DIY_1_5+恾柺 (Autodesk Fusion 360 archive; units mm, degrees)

design "DIY_1_5"
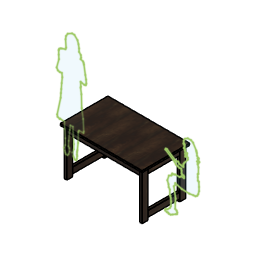
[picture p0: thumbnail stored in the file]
work_plane "作業平面" AlongDistance 675 (= "takasa - 25 mm") named "h1"
sketch "スケッチ2" plane through (0, 0, 675) normal (0, 0, 1) x axis (1, 0, 0)
  line L1 (600, 350) -> (-600, 350)
  line L2 (600, -350) -> (600, 350)
  line L3 (-600, -350) -> (600, -350)
  line L4 (-600, 350) -> (-600, -350)
  line L5 (0, 22.5) -> (0, 1.75)
  line L6 (22.5, 0) -> (1.75, 0)
  point P2 (-600, 350)
  point P3 (600, 350)
  point P5 (-600, -350)
  horizontal L1
  vertical L2
  horizontal L3
  vertical L4
  symmetric L2 L4 L5
  symmetric L1 L3 L6
  dimension "x1" distance P2 P3 = 1200 (= "haba")
  dimension "y1" distance P2 P5 = 700 (= "oku")
  dimension "takasa" value = 700
  dimension "haba" value = 1200
  dimension "oku" value = 700
extrude "押し出し1" new body sketch "スケッチ2" profile of L1 L2 L3 L4 along normal blind 25
sketch "スケッチ3" plane through (0, 0, 675) normal (0, 0, -1) x axis (1, 0, 0)
  line L1 (-600, 350) -> (600, 350)
  line L2 (-600, -350) -> (-600, 350)
  line L3 (600, -350) -> (-600, -350)
  line L4 (600, 350) -> (600, -350)
  line L5 (570, 320) -> (532, 320)
  line L6 (570, 231) -> (570, 320)
  line L7 (532, 231) -> (570, 231)
  line L8 (532, 320) -> (532, 231)
  point P6 (532, 320)
  point P7 (570, 320)
  point P8 (570, 231)
  horizontal L5
  vertical L6
  horizontal L7
  vertical L8
  dimension "d6" distance P6 P7 = 38
  dimension "d7" distance P7 P8 = 89
  dimension "d8" distance L1 L5 = 30
  dimension "d9" distance L4 L6 = 30
extrude "押し出し1" new body sketch "スケッチ3" profile of L5 L6 L7 L8 to an object
work_point "作業点5"
fillet "フィレット1" radius 3
component_from_bodies "ボディ -> コンポーネント1"
mirror_component "コンポーネントをミラー化1"
derived_instance "DerivedInstance1"
derived_instance "DerivedInstance2"
remove_instance "RemoveInstance1"
mirror_component "コンポーネントをミラー化2"
derived_instance "DerivedInstance3"
derived_instance "DerivedInstance4"
sketch "スケッチ4" plane through (0, 0, 675) normal (0, 0, 1) x axis (1, 0, 0)
  line L1 (-532, -234) -> (-532, -317)
  line L2 (532, -234) -> (532, -317)
  line L3 (532, -315) -> (-532, -315)
  line L4 (532, -277) -> (532, -315)
  line L5 (-532, -277) -> (532, -277)
  line L6 (-532, -315) -> (-532, -277)
  line L7 (-600, -350) -> (600, -350)
  point P8 (532, -277)
  point P6 (-532, -315)
  horizontal L3
  vertical L4
  horizontal L5
  vertical L6
  coincident L2 P8
  coincident L1 P6
  dimension "d14" distance L3 L7 = 35
  dimension "d15" distance L3 L5 = 38
extrude "押し出し1" new body sketch "スケッチ4" profile of L3 L4 L5 L6 against normal blind 89
work_point "作業点3"
fillet "フィレット1" radius 3
mirror_component "コンポーネントをミラー化3"
derived_instance "DerivedInstance5"
sketch "スケッチ5" plane through (0, 0, 675) normal (0, 0, 1) x axis (1, 0, 0)
  line L1 (567, -231) -> (535, -231)
  line L2 (567, 231) -> (535, 231)
  line L3 (532, -231) -> (570, -231)
  line L4 (532, 231) -> (532, -231)
  line L5 (570, 231) -> (532, 231)
  line L6 (570, -231) -> (570, 231)
  line L7 (600, -350) -> (600, 350)
  point P8 (532, 231)
  point P6 (570, -231)
  horizontal L3
  vertical L4
  horizontal L5
  vertical L6
  coincident L2 P8
  coincident L1 P6
  dimension "d20" distance L6 L7 = 30
  dimension "d21" distance L4 L6 = 38
extrude "押し出し1" new body sketch "スケッチ5" profile of L3 L4 L5 L6 against normal blind 89
fillet "フィレット1" radius 3
mirror_component "コンポーネントをミラー化4"
derived_instance "DerivedInstance6"
work_point "作業点1"
chamfer "面取り1" distance 5
chamfer "面取り2" distance 3
sketch "スケッチ6" plane through (0, 231, 0) normal (0, -1, 0) x axis (1, 0, 0)
  line L1 (535, 0) -> (535, 675)
  line L2 (567, 0) -> (535, 0)
  line L3 (567, 675) -> (567, 0)
  line L4 (535, 675) -> (567, 675)
  line L5 (570, 0) -> (570, 675)
  line L6 (532, 675) -> (532, 0)
  line L7 (532, 35) -> (570, 35)
  line L8 (532, 124) -> (532, 35)
  line L9 (570, 124) -> (532, 124)
  line L10 (570, 35) -> (570, 124)
  point P12 (532, 124)
  point P10 (570, 35)
  point P13 (570, 124)
  horizontal L7
  vertical L8
  horizontal L9
  vertical L10
  coincident L6 P12
  coincident L5 P10
  dimension "d72" distance L2 L7 = 35
  dimension "d73" distance P10 P13 = 89
extrude "押し出し1" new body sketch "スケッチ6" profile of L1 L3 L7 L8 L9 L10 to an object
fillet "フィレット1" radius 3
mirror_component "コンポーネントをミラー化5"
derived_instance "DerivedInstance7"
sketch "スケッチ7" plane through (0, 0, 0) normal (0, 1, 0) x axis (1, 0, 0)
  line L1 (-500, 0) -> (0, 0)
  line L2 (-500, -400) -> (-500, 0)
  line L3 (-300, -400) -> (-500, -400)
  line L4 (-300, -1600) -> (-300, -400)
  line L5 (0, -1600) -> (-300, -1600)
  line L6 (0, 0) -> (0, -1600)
  point P1 (0, 0)
  point P2 (0, 0)
  point P8 (0, 0)
  point P3 (-500, 0)
  point P4 (-500, -400)
  point P7 (0, -1600)
  point P6 (-300, -1600)
  point P5 (-300, -400)
  coincident P1 P2
  horizontal L1
  perpendicular L1 L2
  perpendicular L2 L3
  perpendicular L3 L4
  perpendicular L4 L5
  coincident P1 P8
  perpendicular L1 L6
  dimension "d139" distance P3 P4 = 400
  dimension "d140" distance P7 P8 = 1600
  dimension "d141" distance P6 P7 = 300
  dimension "d142" distance P4 P5 = 200
sketch "スケッチ8" plane through (0, 0, 0) normal (0, 1, 0) x axis (1, 0, 0)
  line L1 (-945.136, -1302.6809) -> (-960.979, -1290.0486)
  line L2 (-925.1626, -1311.6484) -> (-945.136, -1302.6809)
  line L3 (-870.2935, -1330.2367) -> (-925.1626, -1311.6484)
  line L4 (-861.6507, -1353.6859) -> (-870.2935, -1330.2367)
  line L5 (-869.2291, -1456.8486) -> (-861.6507, -1353.6859)
  line L6 (-862.3124, -1501.2995) -> (-869.2291, -1456.8486)
  line L7 (-837.5923, -1542.7914) -> (-862.3124, -1501.2995)
  line L8 (-774.327, -1578.353) -> (-837.5923, -1542.7914)
  line L9 (-739.7271, -1577.3626) -> (-774.327, -1578.353)
  line L10 (-694.2446, -1531.9253) -> (-739.7271, -1577.3626)
  line L11 (-680.4071, -1488.4566) -> (-694.2446, -1531.9253)
  line L12 (-671.5136, -1439.0667) -> (-680.4071, -1488.4566)
  line L13 (-671.5136, -1395.6021) -> (-671.5136, -1439.0667)
  line L14 (-645.8072, -1367.9426) -> (-671.5136, -1395.6021)
  line L15 (-641.8536, -1336.3294) -> (-645.8072, -1367.9426)
  line L16 (-648.7744, -1315.5855) -> (-641.8536, -1336.3294)
  line L17 (-613.78, -1303.9149) -> (-648.7744, -1315.5855)
  line L18 (-604.9851, -1288.5783) -> (-613.78, -1303.9149)
  line L19 (-600.3288, -1270.1462) -> (-604.9851, -1288.5783)
  line L20 (-579.8746, -1149.1493) -> (-600.3288, -1270.1462)
  line L21 (-569.1605, -1095.7966) -> (-579.8746, -1149.1493)
  line L22 (-565.881, -1046.2311) -> (-569.1605, -1095.7966)
  line L23 (-573.3812, -1022.4984) -> (-565.881, -1046.2311)
  line L24 (-594.7149, -1016.7047) -> (-573.3812, -1022.4984)
  line L25 (-633.6876, -1022.5004) -> (-594.7149, -1016.7047)
  line L26 (-649.1196, -1028.5674) -> (-633.6876, -1022.5004)
  line L27 (-645.5524, -968.1152) -> (-649.1196, -1028.5674)
  line L28 (-649.1607, -952.4859) -> (-645.5524, -968.1152)
  line L29 (-637.5096, -875.829) -> (-649.1607, -952.4859)
  line L30 (-632.7588, -703.3576) -> (-637.5096, -875.829)
  line L31 (-611.7457, -575.5405) -> (-632.7588, -703.3576)
  line L32 (-602.2974, -420.6044) -> (-611.7457, -575.5405)
  line L33 (-606.9989, -399.9005) -> (-602.2974, -420.6044)
  line L34 (-671.9164, -398.1447) -> (-606.9989, -399.9005)
  line L35 (-679.7988, -384.7942) -> (-671.9164, -398.1447)
  line L36 (-683.5962, -369.2347) -> (-679.7988, -384.7942)
  line L37 (-685.8936, -234.2893) -> (-683.5962, -369.2347)
  line L38 (-696.3364, -138.2766) -> (-685.8936, -234.2893)
  line L39 (-701.2846, -113.1856) -> (-696.3364, -138.2766)
  line L40 (-702.7435, -80.7423) -> (-701.2846, -113.1856)
  line L41 (-699.2913, -62.3573) -> (-702.7435, -80.7423)
  line L42 (-705.0203, -23.4052) -> (-699.2913, -62.3573)
  line L43 (-715.5659, -1.7736) -> (-705.0203, -23.4052)
  line L44 (-737.442, -0.5006) -> (-715.5659, -1.7736)
  line L45 (-752.2371, -20.1082) -> (-737.442, -0.5006)
  line L46 (-759.2113, -31.9997) -> (-752.2371, -20.1082)
  line L47 (-770.1638, -72.8166) -> (-759.2113, -31.9997)
  line L48 (-751.3289, -121.3588) -> (-770.1638, -72.8166)
  line L49 (-749.3439, -188.7205) -> (-751.3289, -121.3588)
  line L50 (-757.2715, -275.8922) -> (-749.3439, -188.7205)
  line L51 (-762.2279, -402.6952) -> (-757.2715, -275.8922)
  line L52 (-798.6936, -401.2701) -> (-762.2279, -402.6952)
  line L53 (-806.3624, -339.5449) -> (-798.6936, -401.2701)
  line L54 (-822.1109, -194.1372) -> (-806.3624, -339.5449)
  line L55 (-826.6686, -123.3397) -> (-822.1109, -194.1372)
  line L56 (-813.7846, -105.5065) -> (-826.6686, -123.3397)
  line L57 (-809.8187, -61.9227) -> (-813.7846, -105.5065)
  line L58 (-824.174, -25.5546) -> (-809.8187, -61.9227)
  line L59 (-840.5225, -2.5277) -> (-824.174, -25.5546)
  line L60 (-865.333, -2.4856) -> (-840.5225, -2.5277)
  line L61 (-873.7744, -17.9865) -> (-865.333, -2.4856)
  line L62 (-881.3405, -38.076) -> (-873.7744, -17.9865)
  line L63 (-890.1189, -73.8071) -> (-881.3405, -38.076)
  line L64 (-874.2388, -113.9993) -> (-890.1189, -73.8071)
  line L65 (-872.9196, -200.6491) -> (-874.2388, -113.9993)
  line L66 (-882.1912, -314.5289) -> (-872.9196, -200.6491)
  line L67 (-885.1625, -404.675) -> (-882.1912, -314.5289)
  line L68 (-948.695, -410.1379) -> (-885.1625, -404.675)
  line L69 (-955.3939, -405.76) -> (-948.695, -410.1379)
  line L70 (-986.2827, -416.5604) -> (-955.3939, -405.76)
  line L71 (-992.0076, -443.583) -> (-986.2827, -416.5604)
  line L72 (-940.8659, -679.8077) -> (-992.0076, -443.583)
  line L73 (-937.2124, -740.5949) -> (-940.8659, -679.8077)
  line L74 (-932.1533, -794.6164) -> (-937.2124, -740.5949)
  line L75 (-925.8942, -872.7682) -> (-932.1533, -794.6164)
  line L76 (-917.1363, -951.5447) -> (-925.8942, -872.7682)
  line L77 (-923.5475, -1002.972) -> (-917.1363, -951.5447)
  line L78 (-954.1404, -999.1088) -> (-923.5475, -1002.972)
  line L79 (-981.4661, -1005.9351) -> (-954.1404, -999.1088)
  line L80 (-999.4708, -1034.4803) -> (-981.4661, -1005.9351)
  line L81 (-966.3176, -1155.4741) -> (-999.4708, -1034.4803)
  line L82 (-969.3012, -1212.0673) -> (-966.3176, -1155.4741)
  line L83 (-969.3012, -1266.6734) -> (-969.3012, -1212.0673)
  line L84 (-967.1436, -1276.0447) -> (-969.3012, -1266.6734)
  line L85 (-960.979, -1290.0486) -> (-967.1436, -1276.0447)
  line L86 (995.6824, -1079.475) -> (1042.3032, -1002.9731)
  line L87 (966.1142, -1095.9018) -> (995.6824, -1079.475)
  line L88 (918.2418, -1095.4324) -> (966.1142, -1095.9018)
  line L89 (878.5046, -1069.9318) -> (918.2418, -1095.4324)
  line L90 (859.2618, -1038.4862) -> (878.5046, -1069.9318)
  line L91 (856.2893, -997.6539) -> (859.2618, -1038.4862)
  line L92 (860.9827, -1001.2522) -> (856.2893, -997.6539)
  line L93 (870.3695, -993.2734) -> (860.9827, -1001.2522)
  line L94 (871.1517, -984.9818) -> (870.3695, -993.2734)
  line L95 (871.1517, -962.7665) -> (871.1517, -984.9818)
  line L96 (861.9214, -946.6526) -> (871.1517, -962.7665)
  line L97 (865.8325, -941.8028) -> (861.9214, -946.6526)
  line L98 (877.2531, -937.2659) -> (865.8325, -941.8028)
  line L99 (876.7837, -924.9067) -> (877.2531, -937.2659)
  line L100 (881.3206, -915.3635) -> (876.7837, -924.9067)
  line L101 (880.5384, -883.4486) -> (881.3206, -915.3635)
  line L102 (883.3544, -846.5274) -> (880.5384, -883.4486)
  line L103 (887.8914, -854.5062) -> (883.3544, -846.5274)
  line L104 (898.5297, -877.8166) -> (887.8914, -854.5062)
  line L105 (900.5634, -901.127) -> (898.5297, -877.8166)
  line L106 (908.8551, -900.5012) -> (900.5634, -901.127)
  line L107 (905.5697, -861.7026) -> (908.8551, -900.5012)
  line L108 (919.024, -848.8741) -> (905.5697, -861.7026)
  line L109 (919.024, -825.5637) -> (919.024, -848.8741)
  line L110 (870.5259, -762.9854) -> (919.024, -825.5637)
  line L111 (854.5685, -737.0155) -> (870.5259, -762.9854)
  line L112 (853.6298, -701.3459) -> (854.5685, -737.0155)
  line L113 (826.5647, -704.4748) -> (853.6298, -701.3459)
  line L114 (794.3369, -708.6988) -> (826.5647, -704.4748)
  line L115 (779.7874, -730.6012) -> (794.3369, -708.6988)
  line L116 (762.7348, -724.6563) -> (779.7874, -730.6012)
  line L117 (736.6084, -726.0643) -> (762.7348, -724.6563)
  line L118 (615.9888, -806.008) -> (736.6084, -726.0643)
  line L119 (597.2154, -805.0693) -> (615.9888, -806.008)
  line L120 (591.2704, -790.8328) -> (597.2154, -805.0693)
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as_built_joint "現況"
copy_paste "コピーと貼り付け3"
copy_paste "コピーと貼り付け4"
copy_paste "コピーと貼り付け5"
copy_paste "コピーと貼り付け6"
copy_paste "コピーと貼り付け7"
copy_paste "コピーと貼り付け8"
copy_paste "コピーと貼り付け9"
copy_paste "コピーと貼り付け10"
copy_paste "コピーと貼り付け11"
copy_paste "コピーと貼り付け12"
copy_paste "コピーと貼り付け13"
sketch "スケッチ9" plane through (0, 0, 0) normal (1, 0, 0) x axis (0, 1, 0)
  line L1 (700, 0) -> (0, 0)
  line L2 (700, 25) -> (700, 0)
  line L3 (0, 25) -> (700, 25)
  line L4 (0, 0) -> (0, 25)
  line L5 (-639, 0) -> (-550, 0)
  line L6 (-639, 38) -> (-639, 0)
  line L7 (-550, 38) -> (-639, 38)
  line L8 (-550, 0) -> (-550, 38)
  line L9 (-1378, 0) -> (-1289, 0)
  line L10 (-1378, 38) -> (-1378, 0)
  line L11 (-1289, 38) -> (-1378, 38)
  line L12 (-1289, 0) -> (-1289, 38)
  line L13 (-1667, 0) -> (-1578, 0)
  line L14 (-1667, 38) -> (-1667, 0)
  line L15 (-1578, 38) -> (-1667, 38)
  line L16 (-1578, 0) -> (-1578, 38)
  line L17 (-2406, 0) -> (-2317, 0)
  line L18 (-2406, 38) -> (-2406, 0)
  line L19 (-2317, 38) -> (-2406, 38)
  line L20 (-2317, 0) -> (-2317, 38)
  line L21 (-3145, 0) -> (-3056, 0)
  line L22 (-3145, 38) -> (-3145, 0)
  line L23 (-3056, 38) -> (-3145, 38)
  line L24 (-3056, 0) -> (-3056, 38)
  line L25 (0, 17.9865) -> (0, 2.4856)
  point P1 (0, 0)
  point P2 (0, 0)
  point P4 (700, 25)
  point P5 (0, 25)
  point P3 (700, 0)
  point P6 (-550, 0)
  point P7 (-639, 0)
  point P8 (-639, 38)
  point P10 (-1289, 0)
  point P11 (-1378, 0)
  point P12 (-1378, 38)
  point P14 (-1578, 0)
  point P15 (-1667, 0)
  point P17 (-1578, 38)
  point P18 (-2317, 0)
  point P19 (-2406, 0)
  point P21 (-2317, 38)
  point P22 (-3056, 0)
  point P23 (-3145, 0)
  point P25 (-3056, 38)
  horizontal L1
  vertical L2
  horizontal L3
  vertical L4
  coincident P1 P2
  horizontal L5
  vertical L6
  horizontal L7
  vertical L8
  horizontal L9
  vertical L10
  horizontal L11
  vertical L12
  horizontal L13
  vertical L14
  horizontal L15
  vertical L16
  horizontal L17
  vertical L18
  horizontal L19
  vertical L20
  horizontal L21
  vertical L22
  horizontal L23
  vertical L24
  dimension "d143" distance P4 P5 = 700 (= "oku")
  dimension "d144" distance P3 P4 = 25
  dimension "d145" distance P6 P7 = 89
  dimension "d146" distance P7 P8 = 38
  dimension "d147" distance P10 P11 = 89
  dimension "d148" distance P11 P12 = 38
  dimension "d149" distance L6 L12 = 650
  dimension "d150" distance L10 L16 = 200
  dimension "d151" distance P14 P15 = 89
  dimension "d152" distance P14 P17 = 38
  dimension "d153" distance P18 P19 = 89
  dimension "d154" distance P18 P21 = 38
  dimension "d155" distance L14 L20 = 650
  dimension "d156" distance L18 L24 = 650
  dimension "d157" distance P22 P23 = 89
  dimension "d158" distance P22 P25 = 38
  dimension "d207" distance L8 L25 = 550
extrude "押し出し2" new body sketch "スケッチ9" profile of L1 L2 L3 L4 L5 L6 L7 L8 L9 L10 L11 L12 L13 L14 L15 L16 L17 L18 L19 L20 L21 L22 L23 L24 against normal blind 50 bodies "l1", "l2", "l3", "l4", "l5"
component_from_bodies "ボディ -> コンポーネント2"
component_from_bodies "ボディ -> コンポーネント3"
component_from_bodies "ボディ -> コンポーネント4"
component_from_bodies "ボディ -> コンポーネント5"
component_from_bodies "ボディ -> コンポーネント6"
component_from_bodies "ボディ -> コンポーネント7"
joint "アセンブリ23" alignAngle 0 alignOffsetX 0 alignOffsetY 0 alignOffsetZ 0
joint "アセンブリ24" alignAngle -90 alignOffsetX 0 alignOffsetY 0 alignOffsetZ 0
joint "アセンブリ25" alignAngle 0 alignOffsetX 0 alignOffsetY 0 alignOffsetZ 3
joint "アセンブリ26" alignAngle 180 alignOffsetX 0 alignOffsetY 0 alignOffsetZ 0
joint "アセンブリ27" alignAngle 180 alignOffsetX 0 alignOffsetY 0 alignOffsetZ 3
joint "アセンブリ28" alignAngle 180 alignOffsetX 0 alignOffsetY 0 alignOffsetZ 0
joint "アセンブリ29" alignAngle 180 alignOffsetX 0 alignOffsetY 0 alignOffsetZ 3
joint "アセンブリ30" alignAngle 0 alignOffsetX 0 alignOffsetY 0 alignOffsetZ 0
joint "アセンブリ31" alignAngle 0 alignOffsetX 0 alignOffsetY 0 alignOffsetZ 3
joint "アセンブリ32" alignAngle 0 alignOffsetX 0 alignOffsetY 0 alignOffsetZ 3
joint "アセンブリ33" alignAngle 0 alignOffsetX 0 alignOffsetY 0 alignOffsetZ 3
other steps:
base_feature "基準フィーチャ1"
base_feature "基準フィーチャ1" bodies "l2"
base_feature "基準フィーチャ1" bodies "l3"
base_feature "基準フィーチャ1" bodies "l5"
base_feature "基準フィーチャ1" bodies "l1"
base_feature "基準フィーチャ1" bodies "l4"
derived_base_feature "派生した基準フィーチャ1"
derived_base_feature "派生した基準フィーチャ1"
derived_base_feature "派生した基準フィーチャ1"
derived_base_feature "派生した基準フィーチャ1"
derived_base_feature "派生した基準フィーチャ1"
derived_base_feature "派生した基準フィーチャ1"
derived_base_feature "派生した基準フィーチャ1"
base_feature "基準フィーチャ1"
create_component "CreateComponent1"
create_component "CreateComponent2"
remove_body "RemoveBody1"
create_component "CreateComponent3"
create_component "CreateComponent4"
create_component "CreateComponent5"
create_component "CreateComponent6"
create_component "CreateComponent7"
create_component "CreateComponent8"
create_component "CreateComponent9"
create_component "CreateComponent10"
create_component "CreateComponent11"
create_component "CreateComponent12"
create_component "CreateComponent13"
remove_body "RemoveBody2"
create_component "CreateComponent14"
remove_body "RemoveBody3"
create_component "CreateComponent15"
remove_body "RemoveBody4"
create_component "CreateComponent16"
remove_body "RemoveBody5"
create_component "CreateComponent17"
remove_body "RemoveBody6"
joint_origin "JointOrigin1"
joint_origin "JointOrigin1"
joint_origin "JointOrigin4"
joint_origin "JointOrigin1"
joint_origin "JointOrigin6"
joint_origin "JointOrigin5"
create_component "CreateComponent18"
remove_body "RemoveBody7"
joint_origin "JointOrigin7"
joint_origin "JointOrigin1" sketch "スケッチ9"
joint_origin "JointOrigin6"
joint_origin "JointOrigin8"
joint_origin "JointOrigin6"
joint_origin "JointOrigin2" sketch "スケッチ9"
joint_origin "JointOrigin9"
joint_origin "JointOrigin7"
joint_origin "JointOrigin5"
joint_origin "JointOrigin3" sketch "スケッチ9"
joint_origin "JointOrigin5"
joint_origin "JointOrigin6"
joint_origin "JointOrigin3"
joint_origin "JointOrigin4" sketch "スケッチ9"
joint_origin "JointOrigin5"
joint_origin "JointOrigin4"
named bodies: "l1", "l2", "l3", "l4", "l5"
